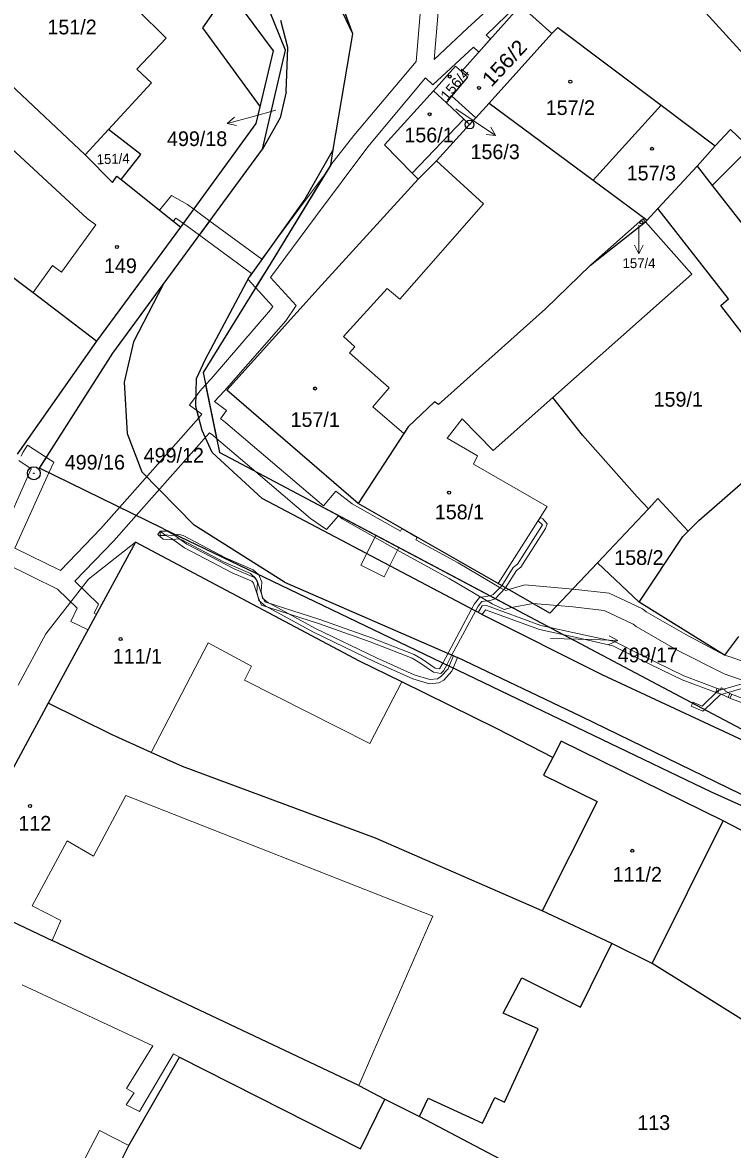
# Model space of a CAD drawing. Extents: x -606517 to -602431, y -1183120 to -1179397.
# Drawn here: x -605471.6 to -605389.6, y -1181000.2 to -1180870.1 of the extents above; entities that cross this region are included whole.
import ezdxf
from ezdxf.enums import TextEntityAlignment as Align

# ---------------------------------------------------------------- set-up
doc = ezdxf.new("R2010")
doc.units = 0
doc.header["$LTSCALE"] = 0.68
for name, color, linetype, lineweight in [('1', 7, 'Continuous', 25), ('13', 7, 'Continuous', 13), ('4', 7, 'Continuous', 13), ('5', 7, 'Continuous', 25), ('7', 7, 'Continuous', 13), ('8', 7, 'Continuous', 25)]:
    doc.layers.add(name, color=color, linetype=linetype, lineweight=lineweight)
doc.layers.add('2', color=7, linetype='Continuous')

msp = doc.modelspace()

# ---------------------------------------------------------------- linework, layer by layer
at = {"layer": '1'}
for p, q in [((-605442.62, -1180873.35), (-605465.77, -1180841.98)), ((-605441.2, -1180873.28), (-605444.9, -1180864.13)), ((-605433.45, -1180871.4), (-605436.03, -1180864.23)), ((-605448.98, -1180868.1), (-605450.8, -1180870.69)), ((-605433.45, -1180871.4), (-605435.03, -1180868.09)), ((-605420.88, -1180875.72), (-605414.08, -1180868.1)), ((-605414.08, -1180868.1), (-605410.46, -1180871.34)), ((-605458.34, -1180868.59), (-605455.01, -1180871.88)), ((-605450.8, -1180870.69), (-605444.14, -1180879.8)), ((-605440.96, -1180872.97), (-605441.75, -1180869.86)), ((-605410.46, -1180871.34), (-605409.75, -1180870.66)), ((-605409.75, -1180870.66), (-605397.82, -1180879.63)), ((-605455.01, -1180871.88), (-605458.39, -1180875.46)), ((-605435.7, -1180884.75), (-605433.45, -1180871.4)), ((-605417.69, -1180879.39), (-605410.46, -1180871.34)), ((-605444.14, -1180879.8), (-605442.62, -1180873.35)), ((-605443.86, -1180884.71), (-605441.2, -1180873.28)), ((-605441.15, -1180878.08), (-605440.96, -1180872.97)), ((-605458.39, -1180875.46), (-605456.7, -1180877.06)), ((-605424.12, -1180877.95), (-605421.57, -1180875.13)), ((-605421.57, -1180875.13), (-605420.88, -1180875.72)), ((-605420.15, -1180876.38), (-605420.88, -1180875.72)), ((-605473.01, -1180877.18), (-605464.36, -1180885.37)), ((-605456.7, -1180877.06), (-605461.66, -1180882.44)), ((-605441.15, -1180878.08), (-605441.83, -1180881.09)), ((-605429.8, -1180884.21), (-605424.12, -1180877.95)), ((-605424.12, -1180877.95), (-605422.64, -1180879.34)), ((-605422.02, -1180878.6), (-605419.24, -1180881.09)), ((-605444.59, -1180881.74), (-605444.14, -1180879.8)), ((-605420.63, -1180881.22), (-605422.64, -1180879.34)), ((-605419.24, -1180881.09), (-605417.69, -1180879.39)), ((-605417.69, -1180879.39), (-605405.68, -1180888.3)), ((-605405.68, -1180888.3), (-605397.82, -1180879.63)), ((-605397.82, -1180879.63), (-605391.6, -1180884.31)), ((-605441.83, -1180881.09), (-605443.86, -1180884.71)), ((-605420.63, -1180881.22), (-605419.95, -1180881.87)), ((-605419.95, -1180881.87), (-605419.24, -1180881.09)), ((-605461.66, -1180882.44), (-605464.36, -1180885.37)), ((-605457.91, -1180885.33), (-605461.66, -1180882.44)), ((-605453.3, -1180893.72), (-605444.59, -1180881.74)), ((-605423.76, -1180886.04), (-605419.95, -1180881.87)), ((-605391.6, -1180884.31), (-605389.82, -1180882.42)), ((-605389.82, -1180882.42), (-605387.6, -1180884.54)), ((-605460.19, -1180888.2), (-605457.91, -1180885.33)), ((-605455.33, -1180900.35), (-605443.86, -1180884.71)), ((-605435.7, -1180884.75), (-605438.98, -1180890.49)), ((-605436, -1180886.5), (-605435.7, -1180884.75)), ((-605426.57, -1180887.49), (-605429.8, -1180884.21)), ((-605393.69, -1180886.66), (-605391.6, -1180884.31)), ((-605464.36, -1180885.37), (-605461.2, -1180888.55)), ((-605436, -1180886.5), (-605443, -1180898)), ((-605425.89, -1180888.18), (-605423.76, -1180886.04)), ((-605461.2, -1180888.55), (-605460.68, -1180887.82)), ((-605460.68, -1180887.82), (-605460.19, -1180888.2)), ((-605425.89, -1180888.18), (-605426.57, -1180887.49)), ((-605393.69, -1180886.66), (-605398.21, -1180891.57)), ((-605393.69, -1180886.66), (-605391.94, -1180888.9)), ((-605460.19, -1180888.2), (-605453.3, -1180893.72)), ((-605437.45, -1180900.85), (-605425.89, -1180888.18)), ((-605405.68, -1180888.3), (-605399.45, -1180892.92)), ((-605391.94, -1180888.9), (-605387.53, -1180894.54)), ((-605438.98, -1180890.49), (-605445.42, -1180899.49)), ((-605399.45, -1180892.92), (-605398.21, -1180891.57)), ((-605390.04, -1180901.99), (-605398.21, -1180891.57)), ((-605463.01, -1180906.86), (-605453.3, -1180893.72)), ((-605443, -1180898), (-605450.73, -1180910.49)), ((-605411.19, -1180903.14), (-605406, -1180898.11)), ((-605473.8, -1180898.68), (-605470.37, -1180901.24)), ((-605450.47, -1180908.96), (-605445.42, -1180899.49)), ((-605461.14, -1180908.27), (-605455.33, -1180900.35)), ((-605455.33, -1180900.35), (-605458.77, -1180906.97)), ((-605447.99, -1180912.52), (-605437.45, -1180900.85)), ((-605470.37, -1180901.24), (-605463.01, -1180906.86)), ((-605390.95, -1180902.75), (-605390.04, -1180901.99)), ((-605423.55, -1180914.18), (-605411.19, -1180903.14)), ((-605380.49, -1180916.41), (-605390.95, -1180902.75)), ((-605472.17, -1180919.93), (-605463.01, -1180906.86)), ((-605458.77, -1180906.97), (-605459.86, -1180911.59)), ((-605469.62, -1180921.53), (-605461.14, -1180908.27)), ((-605451.48, -1180911.17), (-605450.47, -1180908.96)), ((-605451.59, -1180914.43), (-605451.48, -1180911.17)), ((-605450.73, -1180910.49), (-605448.83, -1180919.75)), ((-605459.86, -1180911.59), (-605459.51, -1180917.54)), ((-605432.83, -1180925.63), (-605447.99, -1180912.52)), ((-605424.01, -1180913.89), (-605427.06, -1180916.77)), ((-605423.55, -1180914.18), (-605424.01, -1180913.89)), ((-605406.93, -1180917.72), (-605410.35, -1180913.39)), ((-605450.85, -1180917.2), (-605451.59, -1180914.43)), ((-605459.51, -1180917.54), (-605457.79, -1180921.97)), ((-605449.69, -1180919.75), (-605450.85, -1180917.2)), ((-605427.57, -1180917.55), (-605432.83, -1180925.63)), ((-605427.06, -1180916.77), (-605427.57, -1180917.55)), ((-605406.93, -1180917.72), (-605400.6, -1180924.84)), ((-605443.92, -1180925.06), (-605449.69, -1180919.75)), ((-605374.26, -1180959.28), (-605448.83, -1180919.75)), ((-605455.4, -1180928.52), (-605469.62, -1180921.53)), ((-605457.79, -1180921.97), (-605451.75, -1180928.14)), ((-605418.6, -1180938.4), (-605443.92, -1180925.06)), ((-605416.67, -1180934.86), (-605432.83, -1180925.63)), ((-605400.6, -1180924.84), (-605399.3, -1180926.23)), ((-605398.22, -1180925.05), (-605399.3, -1180926.23)), ((-605398.22, -1180925.05), (-605394.7, -1180928.8)), ((-605405.18, -1180932.49), (-605399.3, -1180926.23)), ((-605441.35, -1180934.71), (-605451.75, -1180928.14)), ((-605455.4, -1180928.52), (-605392.05, -1180958.93)), ((-605400.37, -1180937), (-605395.33, -1180929.42)), ((-605395.33, -1180929.42), (-605394.7, -1180928.8)), ((-605458.54, -1180930.09), (-605468.61, -1180948.69)), ((-605432.68, -1180943.81), (-605458.54, -1180930.09)), ((-605405.18, -1180932.49), (-605410.68, -1180938.27)), ((-605400.37, -1180937), (-605405.18, -1180932.49)), ((-605441.35, -1180934.71), (-605421.34, -1180943.39)), ((-605410.68, -1180938.27), (-605416.67, -1180934.86)), ((-605390.51, -1180943.13), (-605400.37, -1180937)), ((-605418.6, -1180938.4), (-605404.67, -1180945.36)), ((-605388.91, -1180940.96), (-605390.51, -1180943.13)), ((-605406.99, -1180950.27), (-605421.34, -1180943.39)), ((-605404.67, -1180945.36), (-605382.78, -1180955.57)), ((-605468.61, -1180948.69), (-605480.37, -1180970.34)), ((-605461.32, -1180952.29), (-605468.61, -1180948.69)), ((-605387.29, -1180959.84), (-605406.99, -1180950.27)), ((-605410.36, -1180954.95), (-605416.77, -1180951.63)), ((-605456.73, -1180954.36), (-605461.32, -1180952.29)), ((-605409.37, -1180953.06), (-605410.36, -1180954.95)), ((-605390.68, -1180962.26), (-605409.37, -1180953.06)), ((-605453.1, -1180956), (-605456.73, -1180954.36)), ((-605410.36, -1180954.95), (-605411.44, -1180957)), ((-605430.81, -1180964.25), (-605453.1, -1180956)), ((-605411.44, -1180957), (-605405.23, -1180960.04)), ((-605392.05, -1180958.93), (-605358.64, -1180974.03)), ((-605405.23, -1180960.04), (-605411.57, -1180972.67)), ((-605398.87, -1180978.74), (-605390.68, -1180962.26)), ((-605386.24, -1180964.56), (-605390.68, -1180962.26)), ((-605411.57, -1180972.67), (-605430.81, -1180964.25)), ((-605480.37, -1180970.34), (-605468.18, -1180976.07)), ((-605403.53, -1180976.45), (-605411.57, -1180972.67)), ((-605432.76, -1180992.81), (-605468.18, -1180976.07)), ((-605407.16, -1180983.78), (-605403.53, -1180976.45)), ((-605398.87, -1180978.74), (-605403.53, -1180976.45)), ((-605394.61, -1180981.41), (-605398.87, -1180978.74)), ((-605416.08, -1180984.49), (-605413.93, -1180980.4)), ((-605413.93, -1180980.4), (-605407.16, -1180983.78)), ((-605377.52, -1180992.12), (-605394.61, -1180981.41)), ((-605412.05, -1180986.27), (-605416.08, -1180984.49)), ((-605415.92, -1180994.74), (-605412.05, -1180986.27)), ((-605459.3, -1180999.75), (-605453.46, -1180989.57)), ((-605453.46, -1180989.57), (-605432.54, -1181000.13)), ((-605432.76, -1180992.81), (-605429.74, -1180994.42)), ((-605432.54, -1181000.13), (-605429.74, -1180994.42)), ((-605429.74, -1180994.42), (-605425.76, -1180996.41)), ((-605425.76, -1180996.41), (-605424.73, -1180994.31)), ((-605424.73, -1180994.31), (-605418.45, -1180997.16)), ((-605418.45, -1180997.16), (-605417.05, -1180994.23)), ((-605417.05, -1180994.23), (-605415.92, -1180994.74)), ((-605425.76, -1180996.41), (-605389.53, -1181015.4)), ((-605463.26, -1181007.59), (-605459.3, -1180999.75))]:
    msp.add_line(p, q, dxfattribs=at)
for points in [[(-605422.64, -1180879.34), (-605422.02, -1180878.6), (-605420.15, -1180876.38)], [(-605410.35, -1180913.39), (-605394.31, -1180899.15), (-605399.66, -1180893.09)], [(-605399.66, -1180893.09), (-605399.96, -1180892.75), (-605406, -1180898.11)], [(-605406, -1180898.11), (-605399.66, -1180893.09), (-605399.45, -1180892.92)], [(-605394.7, -1180928.8), (-605393.48, -1180927.6), (-605382.35, -1180917.9)], [(-605416.77, -1180951.63), (-605427.77, -1180946.23), (-605432.68, -1180943.81)]]:
    msp.add_lwpolyline(points, dxfattribs=at)
at = {"layer": '13'}
for points in [[(-605399.82, -1180861.06), (-605387.56, -1180874.59)], [(-605424.19, -1180877.28), (-605419.52, -1180872.93), (-605418.9, -1180873.5), (-605417.54, -1180871.98), (-605418.03, -1180871.53), (-605408.59, -1180862.33)], [(-605416.63, -1180867.41), (-605420.2, -1180870.74), (-605424.05, -1180874.33), (-605423.55, -1180868.42)], [(-605425.67, -1180869.08), (-605426.14, -1180874.57), (-605433.34, -1180883.14), (-605436, -1180886.5), (-605436.7, -1180887.65), (-605443, -1180898), (-605444.67, -1180900.69), (-605442.67, -1180902.86), (-605442.96, -1180903.24), (-605449.82, -1180911.24), (-605450.44, -1180911.91), (-605449.17, -1180918.11), (-605444.63, -1180921.98), (-605415.12, -1180937.62), (-605412.62, -1180937.16), (-605409.86, -1180937.4), (-605408.04, -1180937.56), (-605404.42, -1180937.98), (-605401.06, -1180939.55), (-605400.71, -1180939.84), (-605395.98, -1180942.54), (-605390.56, -1180945.28), (-605385.92, -1180946.92)], [(-605385.75, -1180944.8), (-605389.74, -1180943.38), (-605390.51, -1180943.13), (-605395, -1180940.74), (-605399.55, -1180938.12), (-605399.98, -1180937.79), (-605403.84, -1180935.98), (-605408.05, -1180935.5), (-605413.56, -1180935.02), (-605415.43, -1180935.57), (-605415.78, -1180935.67), (-605416.36, -1180935.39), (-605421.29, -1180932.49), (-605426.16, -1180929.82), (-605426.01, -1180929.53), (-605427.77, -1180928.52), (-605427.93, -1180928.83), (-605433.53, -1180925.66), (-605435.39, -1180924.21), (-605436.82, -1180925.88), (-605437.07, -1180925.71), (-605448.38, -1180916.06), (-605448.72, -1180915.84), (-605448.03, -1180914.89), (-605449.42, -1180913.84), (-605448.3, -1180912.64), (-605441.18, -1180904.54), (-605439.97, -1180902.74), (-605442.95, -1180899.51), (-605437.76, -1180892.52), (-605431.72, -1180884.42), (-605425.04, -1180876.48), (-605424.19, -1180877.28)], [(-605469.62, -1180921.53), (-605468.83, -1180920.3), (-605471.01, -1180918.89), (-605471.56, -1180919.75)], [(-605471.56, -1180919.75), (-605471.75, -1180920.16)], [(-605472.02, -1180920.67), (-605470.57, -1180921.61), (-605474.3, -1180929.86)], [(-605473.49, -1180932.59), (-605467.56, -1180935.5), (-605465.28, -1180937.69), (-605466.01, -1180939.23), (-605464.02, -1180940.22), (-605463.05, -1180938.42), (-605463.31, -1180938.29), (-605462.82, -1180937.23), (-605465.55, -1180934.6), (-605461.04, -1180929.92), (-605458.46, -1180927.02), (-605460.38, -1180926.07), (-605462.56, -1180928.52), (-605467.22, -1180933.36), (-605472.48, -1180930.79), (-605468.54, -1180922.06), (-605469.62, -1180921.53)], [(-605388.49, -1180946.46), (-605391.28, -1180947.27), (-605393.11, -1180949.03), (-605394.16, -1180948.58), (-605394.21, -1180948.7), (-605394.36, -1180949.04), (-605393.01, -1180949.61), (-605392.82, -1180949.44), (-605391.02, -1180947.71), (-605388.51, -1180946.98)], [(-605383.61, -1180949.98), (-605389.92, -1180947.57), (-605390.1, -1180948.03), (-605383.75, -1180950.46)]]:
    msp.add_lwpolyline(points, dxfattribs=at)
for points in [[(-605449.94, -1180893), (-605451.15, -1180894.65), (-605445.13, -1180899.06), (-605445.57, -1180899.71), (-605444.67, -1180900.69), (-605443, -1180898), (-605436.7, -1180887.65), (-605439.59, -1180891.53), (-605443.95, -1180897.41)], [(-605452.99, -1180893.3), (-605451.79, -1180891.64), (-605452.54, -1180891.09), (-605454.38, -1180890.05), (-605455.78, -1180891.74), (-605454.19, -1180893.01), (-605453.9, -1180892.67), (-605453.66, -1180892.81)], [(-605451.79, -1180891.64), (-605452.99, -1180893.3), (-605451.15, -1180894.65), (-605449.94, -1180893)], [(-605460.38, -1180926.07), (-605458.46, -1180927.02), (-605449.99, -1180917.47), (-605449.62, -1180917.72), (-605449.17, -1180918.11), (-605450.44, -1180911.91), (-605451.11, -1180912.63), (-605452.29, -1180914.26), (-605450.89, -1180915.31), (-605451.21, -1180915.74)], [(-605468.83, -1180920.3), (-605469.62, -1180921.53), (-605468.54, -1180922.06), (-605467.99, -1180920.85)], [(-605435.11, -1180927.05), (-605444.63, -1180921.98), (-605438.33, -1180927.35), (-605436.48, -1180928.64)], [(-605435.11, -1180927.05), (-605434.68, -1180927.38), (-605428.02, -1180931.16), (-605422.33, -1180934.27), (-605417.34, -1180937.21), (-605415.96, -1180937.87), (-605415.12, -1180937.62)], [(-605415.81, -1180935.35), (-605414.54, -1180933.35), (-605414.05, -1180932.96), (-605411.21, -1180928.49), (-605411, -1180927.97), (-605411.48, -1180927.4), (-605411.77, -1180927.22), (-605412.04, -1180927.64), (-605411.55, -1180928.1), (-605414.43, -1180932.62), (-605414.92, -1180933.01), (-605416.24, -1180935.11)], [(-605455.96, -1180929.21), (-605455.34, -1180929.73), (-605454.3, -1180929.83), (-605453.64, -1180929.69), (-605453.2, -1180929.8), (-605448.36, -1180932.34), (-605445.24, -1180933.7), (-605444.66, -1180934.27), (-605444.46, -1180934.77), (-605444.54, -1180935.81), (-605444.3, -1180936.83), (-605443.57, -1180937.42), (-605437.99, -1180940.48), (-605430.91, -1180943.9), (-605426.53, -1180945.85), (-605424.6, -1180946.44), (-605423.5, -1180946.34), (-605422.95, -1180946.01), (-605422.01, -1180945), (-605421.85, -1180944.62), (-605421.34, -1180943.39), (-605421.8, -1180943.19), (-605422.3, -1180944.41), (-605422.43, -1180944.72), (-605423.27, -1180945.61), (-605423.66, -1180945.86), (-605424.54, -1180945.94), (-605426.35, -1180945.39), (-605430.69, -1180943.44), (-605437.77, -1180940.04), (-605443.29, -1180937), (-605443.86, -1180936.55), (-605444.04, -1180935.77), (-605443.96, -1180934.69), (-605444.29, -1180933.85), (-605444.96, -1180933.28), (-605448.14, -1180931.89), (-605453.02, -1180929.32), (-605453.64, -1180929.17), (-605453.91, -1180929.23), (-605454.34, -1180929.33), (-605455.14, -1180929.25), (-605455.7, -1180928.81)], [(-605455.7, -1180928.81), (-605455.68, -1180929.31), (-605455.04, -1180929.32), (-605454.38, -1180929.66), (-605452.88, -1180930.73), (-605447.37, -1180933.64), (-605445.11, -1180934.6), (-605444.93, -1180934.81), (-605444.34, -1180936.56), (-605443.97, -1180937.37), (-605437.41, -1180939.48), (-605431.45, -1180941.61), (-605426.58, -1180943.48), (-605425.72, -1180944.03), (-605424.12, -1180945.08), (-605423.26, -1180945.26), (-605422.96, -1180944.93), (-605422.6, -1180944.26), (-605421.99, -1180943.11), (-605422.45, -1180942.91), (-605423.06, -1180944.05), (-605423.42, -1180944.72), (-605423.92, -1180944.62), (-605425.44, -1180943.61), (-605426.36, -1180943.04), (-605431.27, -1180941.15), (-605437.25, -1180939), (-605443.61, -1180936.97), (-605443.88, -1180936.38), (-605444.49, -1180934.57), (-605444.81, -1180934.18), (-605447.15, -1180933.18), (-605452.62, -1180930.31), (-605454.11, -1180929.24), (-605454.94, -1180928.83)], [(-605432.5, -1180932.74), (-605429.82, -1180934.08), (-605428.14, -1180930.72), (-605430.79, -1180929.31)], [(-605419.28, -1180938.04), (-605418.98, -1180937.48), (-605418.56, -1180936.94), (-605417.59, -1180936.83), (-605417, -1180936.63), (-605415.81, -1180935.35), (-605416.24, -1180935.11), (-605417.22, -1180936.13), (-605417.61, -1180936.3), (-605418.82, -1180936.46), (-605419.4, -1180937.2), (-605419.72, -1180937.81)], [(-605419.72, -1180937.81), (-605422.45, -1180942.91), (-605421.99, -1180943.11), (-605419.28, -1180938.04)], [(-605418.96, -1180938.21), (-605418.5, -1180938.45), (-605418.12, -1180937.9), (-605411.87, -1180940.18), (-605409.22, -1180940.75), (-605408.12, -1180940.98), (-605403.4, -1180942.05), (-605400.24, -1180943.62), (-605395.4, -1180945.99), (-605391.3, -1180947.53), (-605391.13, -1180947.06), (-605395.2, -1180945.53), (-605400.02, -1180943.18), (-605403.24, -1180941.57), (-605408.02, -1180940.5), (-605410.84, -1180939.89), (-605411.73, -1180939.7), (-605418.02, -1180937.39), (-605418.51, -1180937.43)], [(-605391.51, -1180947.45), (-605390.98, -1180947.59), (-605389.89, -1180948.11), (-605389.67, -1180947.67), (-605390.49, -1180947.26), (-605390.43, -1180947.15), (-605390.88, -1180946.92), (-605391, -1180947.07), (-605391.39, -1180946.97)]]:
    msp.add_lwpolyline(points, close=True, dxfattribs=at)
at = {"layer": '4'}
for p, q in [((-605476.73, -1180881.05), (-605464.14, -1180892.71)), ((-605426.57, -1180887.49), (-605420.63, -1180881.22)), ((-605391.94, -1180888.9), (-605387.6, -1180884.54)), ((-605423.76, -1180886.04), (-605418.36, -1180891.01)), ((-605418.36, -1180891.01), (-605428.03, -1180902.04)), ((-605464.14, -1180892.71), (-605463.13, -1180893.45)), ((-605463.13, -1180893.45), (-605467.1, -1180898.89)), ((-605468.13, -1180898.13), (-605470.37, -1180901.24)), ((-605467.1, -1180898.89), (-605468.13, -1180898.13)), ((-605429.48, -1180900.78), (-605434.52, -1180906.35)), ((-605428.03, -1180902.04), (-605429.48, -1180900.78)), ((-605429.23, -1180912.25), (-605433.82, -1180908.23)), ((-605431.13, -1180914.46), (-605429.23, -1180912.25)), ((-605427.57, -1180917.55), (-605431.13, -1180914.46)), ((-605420.82, -1180915.83), (-605422.02, -1180917.37)), ((-605422.02, -1180917.37), (-605422.56, -1180918.06)), ((-605422.56, -1180918.06), (-605419.05, -1180920.12)), ((-605419.05, -1180920.12), (-605419.49, -1180921.08)), ((-605419.49, -1180921.08), (-605410.98, -1180925.98)), ((-605410.98, -1180925.98), (-605416.67, -1180934.86)), ((-605463.97, -1180934.37), (-605458.54, -1180930.09)), ((-605468.9, -1180940.66), (-605463.97, -1180934.37)), ((-605472.09, -1180946.61), (-605468.9, -1180940.66)), ((-605456.73, -1180954.36), (-605450.15, -1180941.71)), ((-605450.15, -1180941.71), (-605445.13, -1180944.39)), ((-605445.13, -1180944.39), (-605445.95, -1180946.01)), ((-605445.95, -1180946.01), (-605431.48, -1180953.32)), ((-605431.48, -1180953.32), (-605427.77, -1180946.23)), ((-605459.66, -1180959.33), (-605463.39, -1180966.35)), ((-605424.21, -1180973.26), (-605459.66, -1180959.33)), ((-605466.42, -1180964.56), (-605470.46, -1180972.1)), ((-605463.39, -1180966.35), (-605466.42, -1180964.56)), ((-605470.46, -1180972.1), (-605467.17, -1180973.79)), ((-605467.17, -1180973.79), (-605468.18, -1180976.07)), ((-605424.83, -1180974.67), (-605424.21, -1180973.26)), ((-605431.02, -1180988.83), (-605424.83, -1180974.67)), ((-605471.61, -1180981.19), (-605456.55, -1180988.23)), ((-605456.55, -1180988.23), (-605459.56, -1180993.16)), ((-605458.08, -1180995.84), (-605454.14, -1180989.17)), ((-605454.14, -1180989.17), (-605453.46, -1180989.57)), ((-605432.76, -1180992.81), (-605431.02, -1180988.83)), ((-605459.56, -1180993.16), (-605458.69, -1180993.67)), ((-605458.69, -1180993.67), (-605459.6, -1180995.06)), ((-605459.6, -1180995.06), (-605458.08, -1180995.84)), ((-605465.34, -1181003.07), (-605462.68, -1180998.01)), ((-605462.68, -1180998.01), (-605459.3, -1180999.75))]:
    msp.add_line(p, q, dxfattribs=at)
for points in [[(-605434.52, -1180906.35), (-605433.22, -1180907.54), (-605433.82, -1180908.23)], [(-605410.35, -1180913.39), (-605417.25, -1180919.51), (-605420.82, -1180915.83)]]:
    msp.add_lwpolyline(points, dxfattribs=at)
at = {"layer": '5'}
for centre in [(-605422.2468, -1180876.3192), (-605418.8768, -1180877.6292), (-605408.3268, -1180876.9092), (-605424.5768, -1180880.6692), (-605398.8768, -1180884.6592), (-605400.1068, -1180893.1592), (-605460.6868, -1180895.9992), (-605437.7968, -1180912.3392), (-605422.3268, -1180924.3692), (-605460.2668, -1180941.2692), (-605470.7168, -1180960.5492), (-605401.1768, -1180965.7192)]:
    msp.add_circle(centre, 0.175, dxfattribs=at)
at = {"layer": '7'}
for p, q in [((-605447.959, -1180881.747), (-605446.862, -1180881.971)), ((-605416.952, -1180883.138), (-605417.502, -1180882.163)), ((-605400.41, -1180896.771), (-605399.909, -1180895.77)), ((-605402.851, -1180941.435), (-605403.834, -1180940.899))]:
    msp.add_line(p, q, dxfattribs=at)
for points in [[(-605421.54, -1180880.05), (-605419.44, -1180881.46), (-605416.952, -1180883.138), (-605418.062, -1180882.993)], [(-605442.32, -1180880.21), (-605445.06, -1180880.97), (-605447.959, -1180881.747), (-605447.121, -1180881.004)], [(-605400.41, -1180893.46), (-605400.41, -1180893.77), (-605400.41, -1180896.771), (-605400.911, -1180895.77)], [(-605410.6, -1180941.21), (-605405.85, -1180941.33), (-605402.851, -1180941.435), (-605403.869, -1180941.9)]]:
    msp.add_lwpolyline(points, dxfattribs=at)
at = {"layer": '8'}
for centre, radius in [((-605419.95, -1180881.8699), 0.5), ((-605419.95, -1180881.8699), 0.0303), ((-605470.28, -1180922.1298), 0.75), ((-605470.28, -1180922.1298), 0.03)]:
    msp.add_circle(centre, radius, dxfattribs=at)

# ---------------------------------------------------------------- texts
at = {"layer": '2'}
for s, p in [('151/2', (-605468.71, -1180871.445)), ('156/1', (-605427.49, -1180883.915)), ('156/3', (-605419.85, -1180885.855)), ('149', (-605462.18, -1180899.015)), ('499/16', (-605466.71, -1180921.705)), ('158/1', (-605423.97, -1180927.445)), ('158/2', (-605403.25, -1180932.715)), ('111/1', (-605461.17, -1180944.105)), ('499/17', (-605402.85, -1180943.965)), ('112', (-605472.07, -1180963.395)), ('111/2', (-605403.44, -1180969.295)), ('113', (-605400.59, -1180997.965))]:
    msp.add_text(s, height=1.7, dxfattribs=at).set_placement(p)
at = {"layer": '2', "width": 1.1}
msp.add_text('156/2', height=1.7, rotation=47, dxfattribs=at).set_placement((-605417.449, -1180877.619))
msp.add_text('156/4', height=1.139, rotation=50, dxfattribs=at).set_placement((-605421.2053, -1180877.5661), align=Align.CENTER)
at = {"layer": '2'}
for s, height, p in [('157/2', 1.7, (-605408.32, -1180880.755)), ('157/3', 1.7, (-605398.97, -1180888.305)), ('157/4', 1.139, (-605400.39, -1180898.434)), ('159/1', 1.7, (-605395.86, -1180914.442)), ('157/1', 1.7, (-605437.79, -1180916.775)), ('499/12', 1.7, (-605454.12, -1180920.902))]:
    msp.add_text(s, height=height, dxfattribs=at).set_placement(p, align=Align.CENTER)
msp.add_text('499/18', height=1.7, dxfattribs=at).set_placement((-605447.949, -1180884.345), align=Align.RIGHT)
msp.add_text('151/4', height=1.139, rotation=2, dxfattribs=at).set_placement((-605461.0999, -1180886.3883), align=Align.CENTER)

doc.saveas('drawing.dxf')
